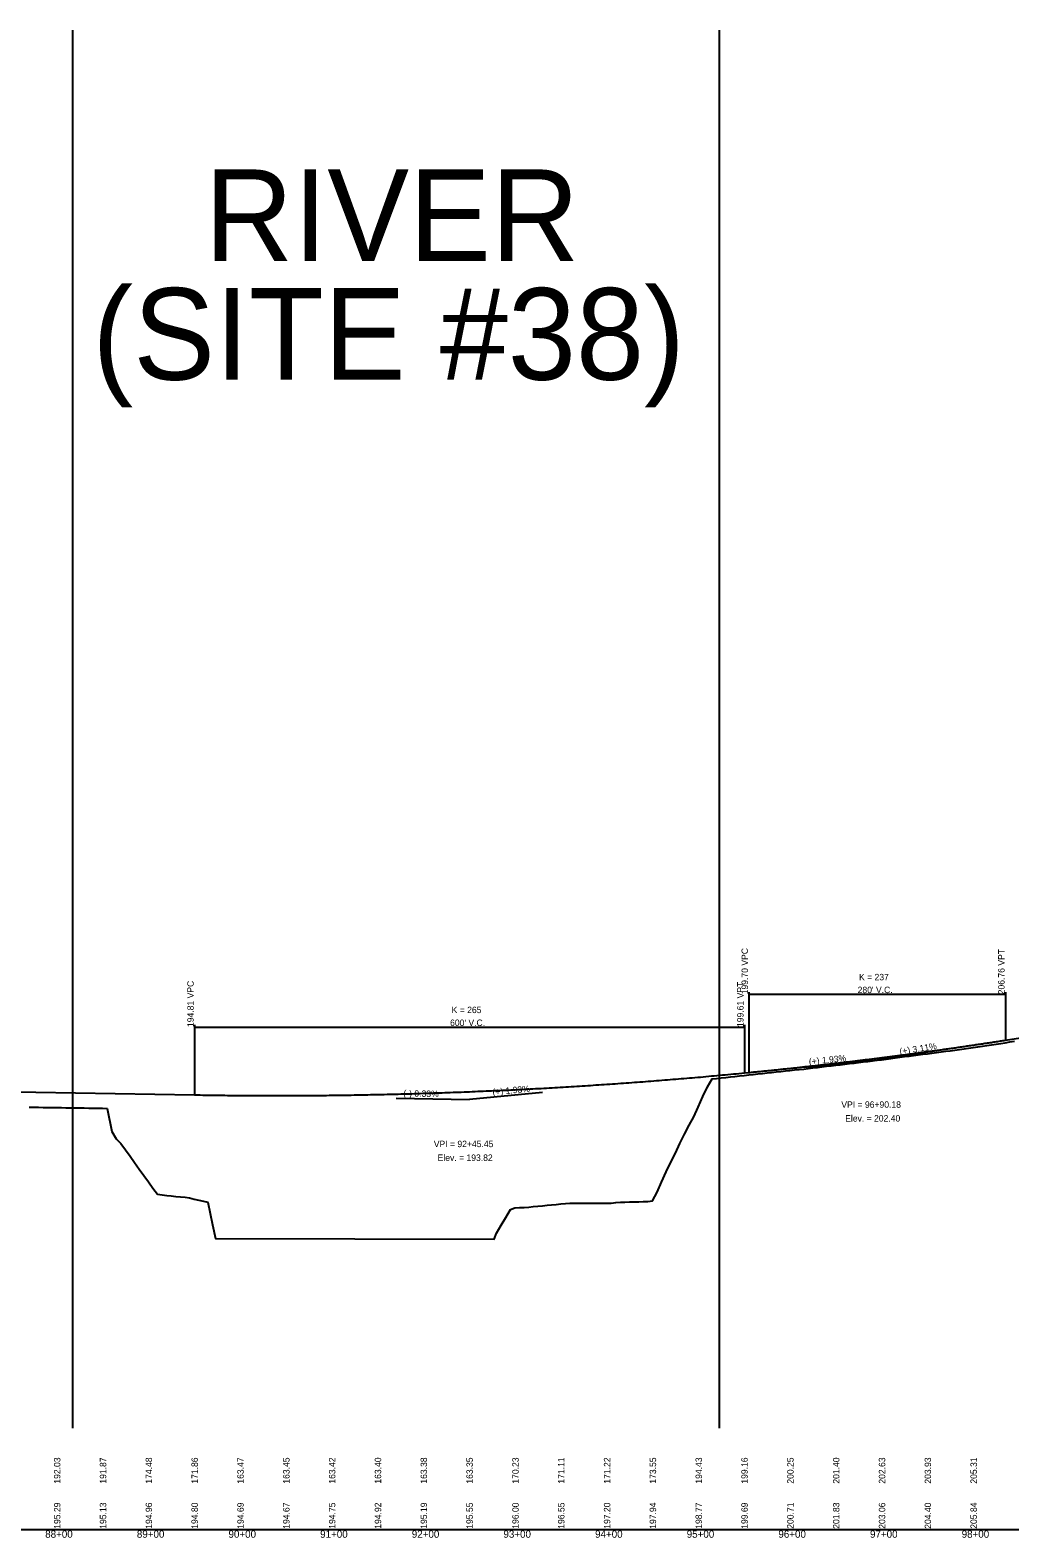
# Model space of a CAD drawing. Extents: x 1838386 to 1955906, y 719739 to 834437.
# Drawn here: x 1886129 to 1887198, y 823083 to 824727 of the extents above; entities that cross this region are included whole.
import ezdxf

# ---------------------------------------------------------------- set-up
doc = ezdxf.new("R2010")
doc.units = 0
for name, color, linetype in [('RD_DDB_GradeTX', 7, 'Continuous'), ('RD_DDB_Profile_EX', 7, 'Continuous'), ('RD_DDB_Profile_Lbl', 7, 'Continuous'), ('RD_DDB_Profile_PR', 7, 'Continuous'), ('RD_DDB_StaTX', 7, 'Continuous'), ('RD_DDB_StripGrade', 7, 'Continuous'), ('RD_DDB_VCLbl', 7, 'Continuous'), ('RD_GPK_Profile_Cell', 7, 'Continuous'), ('RD_Sketch1', 7, 'Continuous')]:
    doc.layers.add(name, color=color, linetype=linetype)

msp = doc.modelspace()

# ---------------------------------------------------------------- linework, layer by layer
at = {"layer": 'RD_DDB_GradeTX'}
for p, q in [((1887132.3, 823615.9), (1887053.3, 823603.6)), ((1886973.6, 823595.9), (1887053.3, 823603.6)), ((1886688.2, 823568.4), (1886608.5, 823560.7)), ((1886528.5, 823562), (1886608.5, 823560.7))]:
    msp.add_line(p, q, dxfattribs=at)
at = {"layer": 'RD_DDB_Profile_EX'}
for points in [[(1886658.1, 823442.5), (1886663.1, 823442.8), (1886668.1, 823443), (1886673.1, 823443.4), (1886678.1, 823443.9), (1886683.1, 823444.3), (1886688.1, 823444.8), (1886693.1, 823445.3), (1886698.1, 823445.8), (1886703.1, 823446.3), (1886708.1, 823446.7), (1886713.1, 823447.2), (1886718.1, 823447.5), (1886723.1, 823447.6), (1886728.1, 823447.6), (1886733.1, 823447.6), (1886738.1, 823447.6), (1886743.1, 823447.6), (1886748.1, 823447.6), (1886753.1, 823447.6), (1886758.1, 823447.6), (1886763.1, 823447.7), (1886768.1, 823448.4), (1886773.1, 823448.6), (1886778.1, 823448.7), (1886783.1, 823448.9), (1886788.1, 823449), (1886793.1, 823449.2), (1886798.1, 823449.3), (1886803.1, 823449.4), (1886808.1, 823450.1), (1886813.1, 823459.4), (1886818.1, 823470.5), (1886823.1, 823481.6), (1886828.1, 823492.3), (1886833.1, 823502.2), (1886838.1, 823512.5), (1886843.1, 823522.9), (1886848.1, 823532.5), (1886853.1, 823541.8), (1886858.1, 823552.4), (1886863.1, 823563.8), (1886868.1, 823574.6), (1886873.1, 823583.1), (1886878.1, 823583.6), (1886883.1, 823584.2), (1886888.1, 823584.7), (1886893.1, 823585.3), (1886898.1, 823585.8), (1886903.1, 823586.3), (1886908.1, 823586.9), (1886913.1, 823587.4), (1886918.1, 823588), (1886923.1, 823588.5), (1886928.1, 823589.1), (1886933.1, 823589.6), (1886938.1, 823590.1), (1886943.1, 823590.7), (1886948.1, 823591.2), (1886953.1, 823591.8), (1886958.1, 823592.3), (1886963.1, 823592.9), (1886968.1, 823593.4), (1886973.1, 823593.9), (1886978.1, 823594.5), (1886983.1, 823595.1), (1886988.1, 823595.7), (1886993.1, 823596.3), (1886998.1, 823596.9), (1887003.1, 823597.4), (1887008.1, 823598), (1887013.1, 823598.6), (1887018.1, 823599.2), (1887023.1, 823599.8), (1887028.1, 823600.4), (1887033.1, 823601), (1887038.1, 823601.6), (1887043.1, 823602.2), (1887048.1, 823602.8), (1887053.1, 823603.5), (1887058.1, 823604.1), (1887063.1, 823604.8), (1887068.1, 823605.4), (1887073.1, 823606.1), (1887078.1, 823606.7), (1887083.1, 823607.4), (1887088.1, 823608), (1887093.1, 823608.7), (1887098.1, 823609.3), (1887103.1, 823610), (1887108.1, 823610.6), (1887113.1, 823611.3), (1887118.1, 823611.9), (1887123.1, 823612.6), (1887128.1, 823613.3), (1887133.1, 823613.9), (1887138.1, 823614.6), (1887143.1, 823615.3), (1887148.1, 823616), (1887153.1, 823616.7), (1887158.1, 823617.4)], [(1887158.1, 823617.4), (1887163.1, 823618.2), (1887168.1, 823618.9), (1887173.1, 823619.7), (1887178.1, 823620.4), (1887183.1, 823621.1), (1887188.1, 823621.9), (1887193.1, 823622.6), (1887198.1, 823623.4), (1887203.1, 823624.2)], [(1886128.1, 823552.4), (1886133.1, 823552.3), (1886138.1, 823552.2), (1886143.1, 823552.1), (1886148.1, 823552), (1886153.1, 823552), (1886158.1, 823551.9), (1886163.1, 823551.8), (1886168.1, 823551.7), (1886173.1, 823551.6), (1886178.1, 823551.5), (1886183.1, 823551.5), (1886188.1, 823551.4), (1886193.1, 823551.3), (1886198.1, 823551.2), (1886203.1, 823551.1), (1886208.1, 823551.1), (1886213.1, 823551), (1886218.1, 823525.9), (1886223.1, 823517.7), (1886228.1, 823512.5), (1886233.1, 823505.6), (1886238.1, 823498.7), (1886243.1, 823491.8), (1886248.1, 823484.8), (1886253.1, 823477.9), (1886258.1, 823471), (1886263.1, 823464), (1886268.1, 823457.3), (1886273.1, 823456.5), (1886278.1, 823456), (1886283.1, 823455.5), (1886288.1, 823455), (1886293.1, 823454.5), (1886298.1, 823454.1), (1886303.1, 823453.3), (1886308.1, 823452.1), (1886313.1, 823450.9), (1886318.1, 823449.7), (1886323.1, 823448.5), (1886328.1, 823424), (1886331.2, 823409), (1886635.3, 823408.3), (1886638.1, 823415), (1886643.1, 823423.6), (1886648.1, 823432.1), (1886653.1, 823440.7), (1886658.1, 823442.5)]]:
    msp.add_lwpolyline(points, dxfattribs=at)
at = {"layer": 'RD_DDB_Profile_PR'}
for p, q in [((1887193.3, 823625.4), (1887372, 823653.2)), ((1886908.5, 823589.7), (1886913.3, 823590.1)), ((1885749.1, 823575), (1886308.5, 823565.7))]:
    msp.add_line(p, q, dxfattribs=at)
for points in [[(1886913.3, 823590.1), (1886918.9, 823590.7), (1886924.5, 823591.2), (1886930.1, 823591.8), (1886935.7, 823592.3), (1886941.3, 823592.9), (1886946.9, 823593.5), (1886952.5, 823594.1), (1886958.1, 823594.6), (1886963.7, 823595.2), (1886969.3, 823595.8), (1886974.9, 823596.5), (1886980.5, 823597.1), (1886986.1, 823597.7), (1886991.7, 823598.3), (1886997.3, 823599), (1887002.9, 823599.6), (1887008.5, 823600.3), (1887014.1, 823600.9), (1887019.7, 823601.6), (1887025.3, 823602.2), (1887030.9, 823602.9), (1887036.5, 823603.6), (1887042.1, 823604.3), (1887047.7, 823605), (1887053.3, 823605.7), (1887058.9, 823606.4), (1887064.5, 823607.1), (1887070.1, 823607.8), (1887075.7, 823608.6), (1887081.3, 823609.3), (1887086.9, 823610), (1887092.5, 823610.8), (1887098.1, 823611.5), (1887103.7, 823612.3), (1887109.3, 823613.1), (1887114.9, 823613.9), (1887120.5, 823614.6), (1887126.1, 823615.4), (1887131.7, 823616.2), (1887137.3, 823617), (1887142.9, 823617.8), (1887148.5, 823618.6), (1887154.1, 823619.5), (1887159.7, 823620.3), (1887165.3, 823621.1), (1887170.9, 823622), (1887176.5, 823622.8), (1887182.1, 823623.7), (1887187.7, 823624.5), (1887193.3, 823625.4)], [(1886308.5, 823565.7), (1886320.5, 823565.5), (1886332.5, 823565.3), (1886344.5, 823565.2), (1886356.5, 823565.1), (1886368.5, 823565), (1886380.5, 823565), (1886392.5, 823564.9), (1886404.5, 823565), (1886416.5, 823565), (1886428.5, 823565), (1886440.5, 823565.1), (1886452.5, 823565.2), (1886464.5, 823565.4), (1886476.5, 823565.5), (1886488.5, 823565.7), (1886500.5, 823566), (1886512.5, 823566.2), (1886524.5, 823566.5), (1886536.5, 823566.8), (1886548.5, 823567.1), (1886560.5, 823567.5), (1886572.5, 823567.9), (1886584.5, 823568.3), (1886596.5, 823568.7), (1886608.5, 823569.2), (1886620.5, 823569.7), (1886632.5, 823570.2), (1886644.5, 823570.7), (1886656.5, 823571.3), (1886668.5, 823571.9), (1886680.5, 823572.5), (1886692.5, 823573.2), (1886704.5, 823573.9), (1886716.5, 823574.6), (1886728.5, 823575.3), (1886740.5, 823576.1), (1886752.5, 823576.9), (1886764.5, 823577.7), (1886776.5, 823578.6), (1886788.5, 823579.4), (1886800.5, 823580.3), (1886812.5, 823581.3), (1886824.5, 823582.2), (1886836.5, 823583.2), (1886848.5, 823584.2), (1886860.5, 823585.2), (1886872.5, 823586.3), (1886884.5, 823587.4), (1886896.5, 823588.5), (1886908.5, 823589.7)]]:
    msp.add_spline(points, degree=3, dxfattribs=at)
at = {"layer": 'RD_DDB_VCLbl'}
for p, q in [((1886913.3, 823677.9), (1886913.3, 823590.1)), ((1886913.3, 823675.4), (1887193.3, 823675.4)), ((1887193.3, 823677.9), (1887193.3, 823625.4)), ((1886308.5, 823642.2), (1886308.5, 823565.7)), ((1886308.5, 823639.7), (1886908.5, 823639.7)), ((1886908.5, 823642.2), (1886908.5, 823589.7))]:
    msp.add_line(p, q, dxfattribs=at)
at = {"layer": 'RD_GPK_Profile_Cell'}
msp.add_line((1878363.1, 823091.6), (1904963.1, 823091.6), dxfattribs=at)
at = {"layer": 'RD_Sketch1'}
for p, q in [((1886175.5, 823202.2), (1886175.5, 824727.1)), ((1886881.2, 823202.2), (1886881.2, 824727.1))]:
    msp.add_line(p, q, dxfattribs=at)

# ---------------------------------------------------------------- texts
at = {"layer": 'RD_DDB_GradeTX'}
for s, rotation, p in [('(+) 3.11%', 8.8476, (1887078.3, 823609.5)), ('(+) 1.93%', 5.5126, (1886979.1, 823598.5)), ('(-) 0.33%', 359.0487, (1886536.3, 823563.9)), ('(+) 1.93%', 5.5126, (1886633.9, 823565.2))]:
    msp.add_text(s, height=7, rotation=rotation, dxfattribs=at).set_placement(p)
at = {"layer": 'RD_DDB_Profile_Lbl'}
for s, p in [('VPI = 96+90.18', (1887014.2, 823551.6)), ('Elev. = 202.40', (1887018.4, 823536.6)), ('VPI = 92+45.45', (1886569.5, 823508.7)), ('Elev. = 193.82', (1886573.7, 823493.7))]:
    msp.add_text(s, height=7, dxfattribs=at).set_placement(p)
at = {"layer": 'RD_DDB_StaTX'}
for s, p in [('88+00', (1886145.5, 823082.6)), ('89+00', (1886245.5, 823082.6)), ('90+00', (1886345.5, 823082.6)), ('91+00', (1886445.5, 823082.6)), ('92+00', (1886545.5, 823082.6)), ('93+00', (1886645.5, 823082.6)), ('94+00', (1886745.5, 823082.6)), ('95+00', (1886845.5, 823082.6)), ('96+00', (1886945.5, 823082.6)), ('97+00', (1887045.5, 823082.6)), ('98+00', (1887145.5, 823082.6))]:
    msp.add_text(s, height=8, dxfattribs=at).set_placement(p)
at = {"layer": 'RD_DDB_StripGrade'}
for s, p in [('199.70 VPC', (1886912.3, 823675.4)), ('206.76 VPT', (1887192.3, 823675.4)), ('194.81 VPC', (1886307.5, 823639.7)), ('199.61 VPT', (1886907.5, 823639.7)), ('192.03', (1886162.1, 823141.6)), ('191.87', (1886212.1, 823141.6)), ('174.48', (1886262.1, 823141.6)), ('171.86', (1886312.1, 823141.6)), ('163.47', (1886362.1, 823141.6)), ('163.45', (1886412.1, 823141.6)), ('163.42', (1886462.1, 823141.6)), ('163.40', (1886512.1, 823141.6)), ('163.38', (1886562.1, 823141.6)), ('163.35', (1886612.1, 823141.6)), ('170.23', (1886662.1, 823141.6)), ('171.11', (1886712.1, 823141.6)), ('171.22', (1886762.1, 823141.6)), ('173.55', (1886812.1, 823141.6)), ('194.43', (1886862.1, 823141.6)), ('199.16', (1886912.1, 823141.6)), ('200.25', (1886962.1, 823141.6)), ('201.40', (1887012.1, 823141.6)), ('202.63', (1887062.1, 823141.6)), ('203.93', (1887112.1, 823141.6)), ('205.31', (1887162.1, 823141.6)), ('195.29', (1886162.1, 823092.4)), ('195.13', (1886212.1, 823092.4)), ('194.96', (1886262.1, 823092.4)), ('194.80', (1886312.1, 823092.4)), ('194.69', (1886362.1, 823092.4)), ('194.67', (1886412.1, 823092.4)), ('194.75', (1886462.1, 823092.4)), ('194.92', (1886512.1, 823092.4)), ('195.19', (1886562.1, 823092.4)), ('195.55', (1886612.1, 823092.4)), ('196.00', (1886662.1, 823092.4)), ('196.55', (1886712.1, 823092.4)), ('197.20', (1886762.1, 823092.4)), ('197.94', (1886812.1, 823092.4)), ('198.77', (1886862.1, 823092.4)), ('199.69', (1886912.1, 823092.4)), ('200.71', (1886962.1, 823092.4)), ('201.83', (1887012.1, 823092.4)), ('203.06', (1887062.1, 823092.4)), ('204.40', (1887112.1, 823092.4)), ('205.84', (1887162.1, 823092.4))]:
    msp.add_text(s, height=7, rotation=90, dxfattribs=at).set_placement(p)
at = {"layer": 'RD_DDB_VCLbl'}
for s, p in [('K = 237', (1887033.5, 823690.7)), ("280' V.C.", (1887032, 823676.7)), ("600' V.C.", (1886587.3, 823640.9)), ('K = 265', (1886589, 823654.9))]:
    msp.add_text(s, height=7, dxfattribs=at).set_placement(p)
at = {"layer": 'RD_Sketch1'}
for s, p in [('RIVER', (1886319.6, 824475.2)), ('(SITE #38)', (1886197, 824345.8))]:
    msp.add_text(s, height=100, dxfattribs=at).set_placement(p)

doc.saveas('drawing.dxf')
